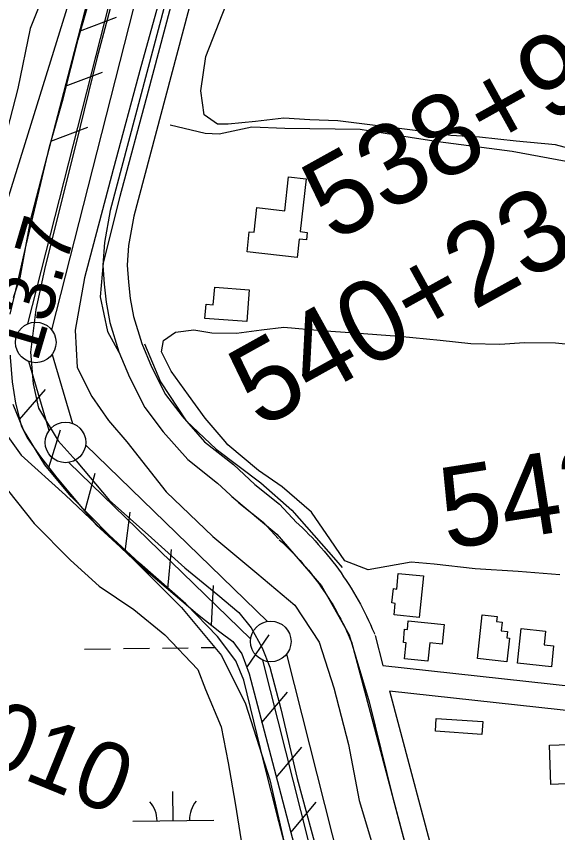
# Model space of a CAD drawing. Extents: x 3715084 to 3753216, y 488173 to 513963.
# Drawn here: x 3735343 to 3736010, y 501479 to 502484 of the extents above; entities that cross this region are included whole.
import ezdxf

# ---------------------------------------------------------------- set-up
doc = ezdxf.new("R2010")
doc.units = 0
for name, color, linetype in [('V-BLDG-OTLN', 7, 'Continuous'), ('V-FLOD-BASE', 7, 'Continuous'), ('V-LEVE-TOET', 7, 'Continuous'), ('V-RIVR-RANG', 7, 'Continuous'), ('V-RIVR-RANG-IDEN', 7, 'Continuous'), ('V-ROAD-CNTR', 7, 'Continuous'), ('V-RRAP-FSHR', 7, 'Continuous'), ('V-SITE-VEGE', 7, 'Continuous'), ('V-SURV-IDEN', 7, 'Continuous'), ('V-SURV-LINE', 7, 'Continuous'), ('V-TOPO-SHOR', 7, 'Continuous'), ('V-WETL-SWMP', 7, 'Continuous')]:
    doc.layers.add(name, color=color, linetype=linetype)

msp = doc.modelspace()

# ---------------------------------------------------------------- linework, layer by layer
at = {"layer": 'V-BLDG-OTLN'}
for points in [[(3735700.1, 502284.3), (3735692.9, 502219.3), (3735701.7, 502218.4), (3735700.7, 502209.2), (3735691.7, 502210.1), (3735689.2, 502187.6), (3735627.5, 502194.4), (3735630.2, 502219.2), (3735636.3, 502218.5), (3735639.6, 502248.8), (3735673.8, 502245), (3735678.4, 502286.7)], [(3735627.1, 502108.4), (3735575.5, 502112.4), (3735576.9, 502129.9), (3735585.8, 502129.3), (3735587.5, 502150.8), (3735630.1, 502147.5)], [(3735813.9, 501798.3), (3735844.8, 501795.1), (3735839.5, 501744), (3735808.6, 501747.2), (3735810.1, 501761.4), (3735806, 501761.9), (3735807.9, 501779.5), (3735811.9, 501779)], [(3735951.1, 501718.4), (3735947.8, 501689.5), (3735911.4, 501693.5), (3735917.3, 501747.1), (3735935.8, 501745), (3735935.1, 501739.1), (3735941.8, 501738.4), (3735940.6, 501727.6), (3735948.4, 501726.7), (3735947.5, 501718.8)], [(3735826.2, 501739.7), (3735870.6, 501735.2), (3735868.1, 501711.1), (3735852.8, 501712.6), (3735850.5, 501690), (3735821.5, 501693), (3735823.5, 501712.8), (3735820.1, 501713.2), (3735821.7, 501729.5), (3735825.1, 501729.2)], [(3736002.6, 501683), (3735960.7, 501687.5), (3735965.3, 501730.5), (3735995.5, 501727.2), (3735993.7, 501710.3), (3736005.4, 501709)], [(3735860.7, 501619.7), (3735918, 501615.8), (3735916.9, 501599.9), (3735859.6, 501603.8)], [(3736047.6, 501588.5), (3736049.5, 501540.2), (3736002.1, 501538.3), (3736000.2, 501586.6)]]:
    msp.add_lwpolyline(points, close=True, dxfattribs=at)
at = {"layer": 'V-FLOD-BASE'}
msp.add_lwpolyline([(3735465.1, 502519), (3735442.3, 502432.4), (3735416.4, 502326.9), (3735378.4, 502176.4), (3735367, 502123.4), (3735360.6, 502070.9), (3735363.8, 502031.7), (3735370.1, 502002), (3735394.7, 501961.5), (3735416.8, 501936.9), (3735457.9, 501888.2), (3735505.3, 501845.8), (3735550.8, 501805.3), (3735591.2, 501771.8), (3735617.1, 501750.3), (3735632.3, 501731.4), (3735646.2, 501706.7), (3735655.7, 501682.7), (3735668.9, 501631.5), (3735689.1, 501545.5), (3735718.2, 501438)], dxfattribs=at)
at = {"layer": 'V-LEVE-TOET'}
for points in [[(3735527.9, 502536.4), (3735496.6, 502422.1), (3735462.2, 502295.9), (3735427.2, 502162.2), (3735415.3, 502097.9), (3735417.8, 502051.7), (3735435.9, 502016), (3735456.5, 501986.7), (3735479, 501960.4), (3735527.7, 501898.6), (3735585.1, 501843.6), (3735639.5, 501798.6), (3735686.3, 501759.2), (3735716.3, 501713.6), (3735734.4, 501657.4), (3735752.4, 501587.4), (3735765.5, 501518.7), (3735796.1, 501417.5)], [(3735335.2, 502117.4), (3735345.8, 502161.2), (3735355.2, 502202.4), (3735369.6, 502263), (3735384, 502323.6), (3735400.9, 502382.9), (3735419, 502456), (3735439.6, 502527.8)], [(3735647.9, 501565.7), (3735623.6, 501666.9), (3735613.6, 501690.7), (3735591.1, 501720.7), (3735551.8, 501760.7), (3735495, 501810.7), (3735456.9, 501845.7), (3735410.7, 501893.2), (3735378.2, 501931.9), (3735352, 501975), (3735338.9, 502006.2)], [(3735783, 500172.6), (3735796.8, 500268.8), (3735813.7, 500366.2), (3735832.4, 500463.7), (3735850, 500576.7), (3735859.4, 500651.1), (3735858.2, 500719.2), (3735845.1, 500797.9), (3735824.5, 500890.4), (3735817.6, 500914.7), (3735812.6, 500928.5), (3735810.1, 500942.8), (3735807, 500957.8), (3735797, 500991.6), (3735780.2, 501051.5), (3735761.5, 501123.4), (3735745.9, 501197.1), (3735731.5, 501256.5), (3735712.2, 501316.4), (3735695.3, 501375.2), (3735683.5, 501428.3), (3735666.7, 501492.6), (3735647.9, 501565.7)]]:
    msp.add_lwpolyline(points, dxfattribs=at)
at = {"layer": 'V-ROAD-CNTR'}
for points in [[(3735698.7, 503148.4), (3735458.6, 502245.1), (3735451.5, 502205.9), (3735449.8, 502177.8), (3735451.3, 502154.4), (3735453.6, 502132.5), (3735458.3, 502107.5), (3735469.3, 502071.2), (3735482.4, 502040), (3735501.5, 502002.6), (3735524.1, 501972.8), (3735554.4, 501938.4), (3735591.1, 501909.6), (3735617.4, 501885), (3735647.1, 501861.5), (3735666.3, 501840.7)], [(3735728, 503141.8), (3735487.9, 502238.5), (3735481.4, 502202.3), (3735479.8, 502177.8), (3735481.2, 502156.9), (3735483.3, 502136.9), (3735487.5, 502114.6), (3735497.6, 502081.3), (3735509.6, 502052.6), (3735527, 502018.6), (3735547.3, 501991.8), (3735575.1, 501960.3), (3735610.6, 501932.4), (3735636.9, 501907.8), (3735667.6, 501883.5), (3735688.4, 501860.9)], [(3735687.4, 501861.9), (3735691.5, 501858.1), (3735695.6, 501854.3), (3735699.7, 501850.3), (3735703.6, 501846.3), (3735707.6, 501842.3), (3735711.4, 501838.2), (3735715.2, 501834), (3735718.9, 501829.8), (3735722.6, 501825.5), (3735726.2, 501821.2), (3735729.8, 501816.8), (3735733.3, 501812.4), (3735736.7, 501807.9), (3735740, 501803.4), (3735743.3, 501798.8), (3735746.5, 501794.2), (3735749.7, 501789.5), (3735752.7, 501784.8), (3735755.7, 501780), (3735758.7, 501775.2), (3735761.5, 501770.3), (3735764.3, 501765.5), (3735767.1, 501760.5), (3735769.7, 501755.5), (3735772.3, 501750.5), (3735774.8, 501745.5), (3735777.2, 501740.4), (3735779.5, 501735.3), (3735781.8, 501730.1), (3735784, 501725), (3735784.5, 501723.6)], [(3735667.2, 501839.7), (3735671.1, 501836.2), (3735674.9, 501832.6), (3735678.6, 501829), (3735682.2, 501825.3), (3735685.8, 501821.6), (3735689.4, 501817.8), (3735692.9, 501814), (3735696.3, 501810.1), (3735699.7, 501806.1), (3735703.1, 501802.2), (3735706.3, 501798.1), (3735709.5, 501794), (3735712.7, 501789.9), (3735715.8, 501785.7), (3735718.8, 501781.5), (3735721.8, 501777.2), (3735724.6, 501772.9), (3735727.5, 501768.6), (3735730.3, 501764.2), (3735733, 501759.8), (3735735.6, 501755.3), (3735738.2, 501750.8), (3735740.7, 501746.2), (3735743.1, 501741.7), (3735745.5, 501737), (3735747.8, 501732.4), (3735750, 501727.7), (3735752.2, 501723), (3735754.3, 501718.2), (3735756.3, 501713.4), (3735756.8, 501712.2)], [(3735795, 501684.8), (3736601.2, 501596.6), (3736611.7, 501593.7), (3736618.8, 501594.8), (3736623.7, 501596.9), (3736628.3, 501599.6), (3736637.5, 501607.8), (3736669.2, 501659.7), (3736743.4, 501742.2)], [(3735785.2, 501721.8), (3735795, 501684.8)], [(3735803.2, 501653.7), (3736595.6, 501567), (3736609.8, 501563.1), (3736627.3, 501565.7), (3736637.4, 501570.2), (3736646.1, 501575.3), (3736660.8, 501588.4), (3736693.4, 501641.7), (3736765.7, 501722.2)], [(3735756.2, 501714.1), (3735907.8, 501142.9)], [(3735803.2, 501653.7), (3735867.5, 501411.5)]]:
    msp.add_lwpolyline(points, dxfattribs=at)
at = {"layer": 'V-RRAP-FSHR'}
for p, q in [((3735420.8, 502466.4), (3735466.6, 502483.4)), ((3735403.2, 502398.6), (3735449, 502415.6)), ((3735385.5, 502330.9), (3735431.3, 502347.9)), ((3735346.9, 501987.9), (3735378.9, 502024.8)), ((3735383.1, 501928.7), (3735397.6, 501975.3)), ((3735427.6, 501874.6), (3735440.3, 501921.8)), ((3735477.1, 501825.4), (3735483.5, 501873.8)), ((3735529.6, 501779.1), (3735534.3, 501827.7)), ((3735583.6, 501734.5), (3735585.9, 501783.2)), ((3735627.2, 501682.2), (3735654.8, 501722.4)), ((3735645.7, 501614.7), (3735677.3, 501651.9)), ((3735663.5, 501547), (3735695.1, 501584.2)), ((3735681.2, 501479.3), (3735712.8, 501516.5))]:
    msp.add_line(p, q, dxfattribs=at)
for points in [[(3735602.6, 504100.7), (3735596.7, 504057.5), (3735589.4, 503978.8), (3735580.3, 503905.2), (3735573, 503817.2), (3735565.8, 503745.6), (3735560.3, 503702.1), (3735556.6, 503655.9), (3735559.9, 503616.7), (3735566, 503570.3), (3735588.7, 503447.1), (3735620.8, 503287.1), (3735621.7, 503265.7), (3735619, 503227), (3735567.3, 503044.5), (3735505.9, 502792.8), (3735359.9, 502232.6), (3735347.3, 502162.3), (3735339.2, 502137.8)], [(3735530, 502891.6), (3735505.9, 502792.8), (3735383.3, 502322.4)], [(3735335.4, 502066.9), (3735335.4, 502064.5), (3735337.8, 502034.2), (3735341.9, 502008), (3735348.8, 501980.3), (3735356.2, 501965.4), (3735372.9, 501941.8), (3735393, 501916), (3735441.3, 501858.2), (3735500, 501804.4), (3735566.2, 501747.9), (3735593.9, 501726.4), (3735609.8, 501714.3), (3735620.9, 501699), (3735630, 501674.6), (3735668.9, 501526.3), (3735730.1, 501292.2), (3735787.3, 501065.7)], [(3735341.9, 502008), (3735348.8, 501980.3), (3735356.2, 501965.4), (3735372.9, 501941.8), (3735393, 501916), (3735441.3, 501858.2), (3735500, 501804.4), (3735566.2, 501747.9), (3735593.9, 501726.4), (3735609.8, 501714.3), (3735620.9, 501699), (3735630, 501674.6), (3735668.9, 501526.3), (3735730.1, 501292.2), (3735787.3, 501065.7)]]:
    msp.add_lwpolyline(points, dxfattribs=at)
at = {"layer": 'V-SITE-VEGE'}
for points in [[(3735386.3, 502535.7), (3735360.2, 502469.5), (3735344.9, 502395.6), (3735325.1, 502319.2)], [(3736051.9, 502314.4), (3736007.9, 502326.1), (3735959.2, 502330.9), (3735913.8, 502335.7), (3735878.8, 502337.8), (3735834.8, 502344), (3735788.8, 502349.5), (3735739.3, 502355.7), (3735705, 502357.1), (3735672.7, 502359.2), (3735637.7, 502355.1), (3735604, 502351.6), (3735590.9, 502351.6), (3735574.5, 502363.3), (3735570.3, 502392.9), (3735576.5, 502434.8), (3735601.3, 502498)], [(3736013.2, 501796.4), (3735961.7, 501800.5), (3735908.8, 501804), (3735858, 501809.5), (3735829.8, 501812.3), (3735799.6, 501806.8), (3735776.9, 501802.7), (3735748.1, 501813.7), (3735730.2, 501839.8), (3735706.9, 501873.5), (3735670.5, 501905.1), (3735641.6, 501925), (3735603.8, 501956.6), (3735600.4, 501960.7), (3735575.7, 501989.6), (3735555.1, 502017.8), (3735533.8, 502047.3), (3735522.1, 502071.4), (3735524.2, 502085.1), (3735539.3, 502095.4), (3735562, 502098.1), (3735584, 502094.7), (3735614.2, 502094), (3735645.1, 502098.1), (3735672.6, 502101.5), (3735719.3, 502097.4), (3735759.8, 502094.6), (3735814.8, 502090.5), (3735865.6, 502085.7), (3735903.4, 502081.5), (3735939.1, 502080.8), (3735969.4, 502082.9), (3736007.8, 502082.2), (3736044.9, 502078.7)], [(3735333.2, 501899.7), (3735365.1, 501859.6), (3735409.6, 501814.4), (3735445.2, 501782.6), (3735487.9, 501753.9), (3735526.1, 501722.7), (3735566.8, 501680), (3735576.3, 501655.2), (3735595.4, 501609.4), (3735604.3, 501564.8), (3735612.6, 501515.1)], [(3735612.6, 501515.1), (3735620.2, 501468.7)]]:
    msp.add_lwpolyline(points, dxfattribs=at)
at = {"layer": 'V-SURV-LINE'}
for points in [[(3735357.3, 502105.8), (3735648.5, 503249.2)], [(3735677.6, 503241.8), (3735386.4, 502098.4)], [(3735387, 502067.9), (3735412.3, 501983.1)], [(3735383.5, 501974.5), (3735358.2, 502059.3)], [(3735428.4, 501956.5), (3735652.7, 501739.1)], [(3735631.8, 501717.5), (3735407.5, 501934.9)], [(3735676, 501698.7), (3735920, 500733.9)], [(3735890.9, 500726.6), (3735647, 501691.4)]]:
    msp.add_lwpolyline(points, dxfattribs=at)
for centre in [(3735366.9, 502082.8), (3735403.6, 501959.6), (3735656.6, 501714.4)]:
    msp.add_circle(centre, 25, dxfattribs=at)
at = {"layer": 'V-TOPO-SHOR'}
for points in [[(3735748.1, 504094.6), (3735735.7, 504008), (3735719.2, 503889.2), (3735702, 503793), (3735683.4, 503678.3), (3735680.6, 503618.5), (3735686.1, 503534.7), (3735696.4, 503465.3), (3735707.3, 503389.1), (3735719, 503306.6), (3735722.4, 503270.9), (3735718.3, 503230.4), (3735709.3, 503165.1), (3735690.1, 503087.5), (3735653.6, 502956.3), (3735615.1, 502808.6), (3735571, 502641), (3735545.6, 502544.1), (3735505.7, 502392.3), (3735470.6, 502262.5), (3735450, 502180.7), (3735446.5, 502138.8), (3735455.4, 502096.2), (3735469.2, 502070.8)], [(3736668.6, 501637), (3736615.7, 501689.3), (3736540.1, 501767.6), (3736455.7, 501854.2), (3736354.7, 501957.3), (3736268.2, 502054.2), (3736224.3, 502114), (3736184.4, 502184.8), (3736161.1, 502241.8), (3736148.1, 502268.6), (3736122, 502283), (3736054, 502299.5), (3735954.3, 502318.1), (3735863, 502329.8), (3735828.6, 502335.3), (3735766.8, 502345), (3735674.1, 502346.4), (3735633.5, 502347.8), (3735593, 502339.5), (3735575.8, 502340.2), (3735532.5, 502350.6)], [(3735500.8, 502081.1), (3735520.7, 502034.4), (3735552.3, 501986.3), (3735589.3, 501951.2), (3735644.3, 501910), (3735682.7, 501876.3), (3735737, 501814.5), (3735744.5, 501805.5)], [(3735608.6, 501892.8), (3735664.2, 501846.8), (3735719.1, 501782.9), (3735753.4, 501722.4), (3735778.1, 501639.9), (3735807, 501521.8), (3735841.9, 501389.9), (3735870.1, 501281.3), (3735901.6, 501159), (3735925, 501070.4), (3735955.8, 500959.1), (3735975.7, 500886.2), (3735993.6, 500797.6), (3735998.3, 500736.5), (3735988.7, 500674)]]:
    msp.add_lwpolyline(points, dxfattribs=at)
at = {"layer": 'V-WETL-SWMP'}
for p, q in [((3735427, 501705.1), (3735459, 501705.5)), ((3735475, 501705.7), (3735507, 501706.1)), ((3735523, 501706.3), (3735555, 501706.7)), ((3735571, 501706.9), (3735587.7, 501707.1)), ((3735536.5, 501493.8), (3735536, 501529.8)), ((3735486.5, 501493.2), (3735586.5, 501494.4))]:
    msp.add_line(p, q, dxfattribs=at)
for points in [[(3735566.4, 503890.4), (3735566.4, 503831.1), (3735566.4, 503781.7), (3735571.4, 503722.4), (3735571.4, 503653.2), (3735581.3, 503539.6), (3735615.8, 503386.5), (3735625.7, 503312.4), (3735620.8, 503253.1), (3735551.6, 503025.9), (3735487.4, 502759.1), (3735304.6, 502171.3)], [(3735324.4, 501978.6), (3735349.1, 501944.1), (3735403.4, 501894.7), (3735487.4, 501815.6)], [(3735487.4, 501815.6), (3735546.7, 501756.4), (3735596.1, 501697.1), (3735625.7, 501637.8), (3735655.4, 501543.9), (3735773.9, 501025.3)]]:
    msp.add_lwpolyline(points, dxfattribs=at)
for centre, start, end in [((3735481.3, 501493.6), 359.9442, 41.4878), ((3735591.7, 501495), 139.9442, 181.4878)]:
    msp.add_arc(centre, 35.2, start, end, dxfattribs=at)

# ---------------------------------------------------------------- texts
at = {"layer": 'V-RIVR-RANG'}
msp.add_text('13.7', height=67, rotation=73.5883, dxfattribs=at).set_placement((3735368.7, 502056.9))
at = {"layer": 'V-RIVR-RANG-IDEN'}
msp.add_text('D-010', height=83, rotation=337.9253, dxfattribs=at).set_placement((3735183.9, 501612.9))
at = {"layer": 'V-SURV-IDEN'}
for s, rotation, p in [('538+95.1', 29.0083, (3735733.8, 502205.3)), ('540+23.6', 28.9867, (3735643.3, 501975.8)), ('543+76.0', 8.8788, (3735873.4, 501827.8))]:
    msp.add_text(s, height=100, rotation=rotation, dxfattribs=at).set_placement(p)

doc.saveas('drawing.dxf')
